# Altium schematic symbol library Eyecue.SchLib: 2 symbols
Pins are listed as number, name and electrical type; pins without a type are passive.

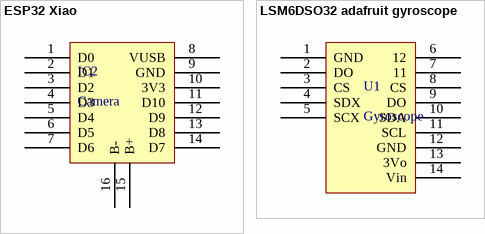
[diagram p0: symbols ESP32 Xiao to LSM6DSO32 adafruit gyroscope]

## ESP32 Xiao
designator IC2, comment Camera
pins: 1 D0, 2 D1, 3 D2, 4 D3, 5 D4, 6 D5, 7 D6, 8 VUSB (power), 9 GND (power), 10 3V3 (power), 11 D10, 12 D9, 13 D8, 14 D7, 15 B+, 16 B-

## LSM6DSO32 adafruit gyroscope
designator U1, comment Gyroscope
pins: 1 GND (power), 2 DO, 3 CS, 4 SDX, 5 SCX, 6 12, 7 11, 8 CS, 9 DO, 10 SDA, 11 SCL, 12 GND (power), 13 3Vo (power), 14 Vin (power)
